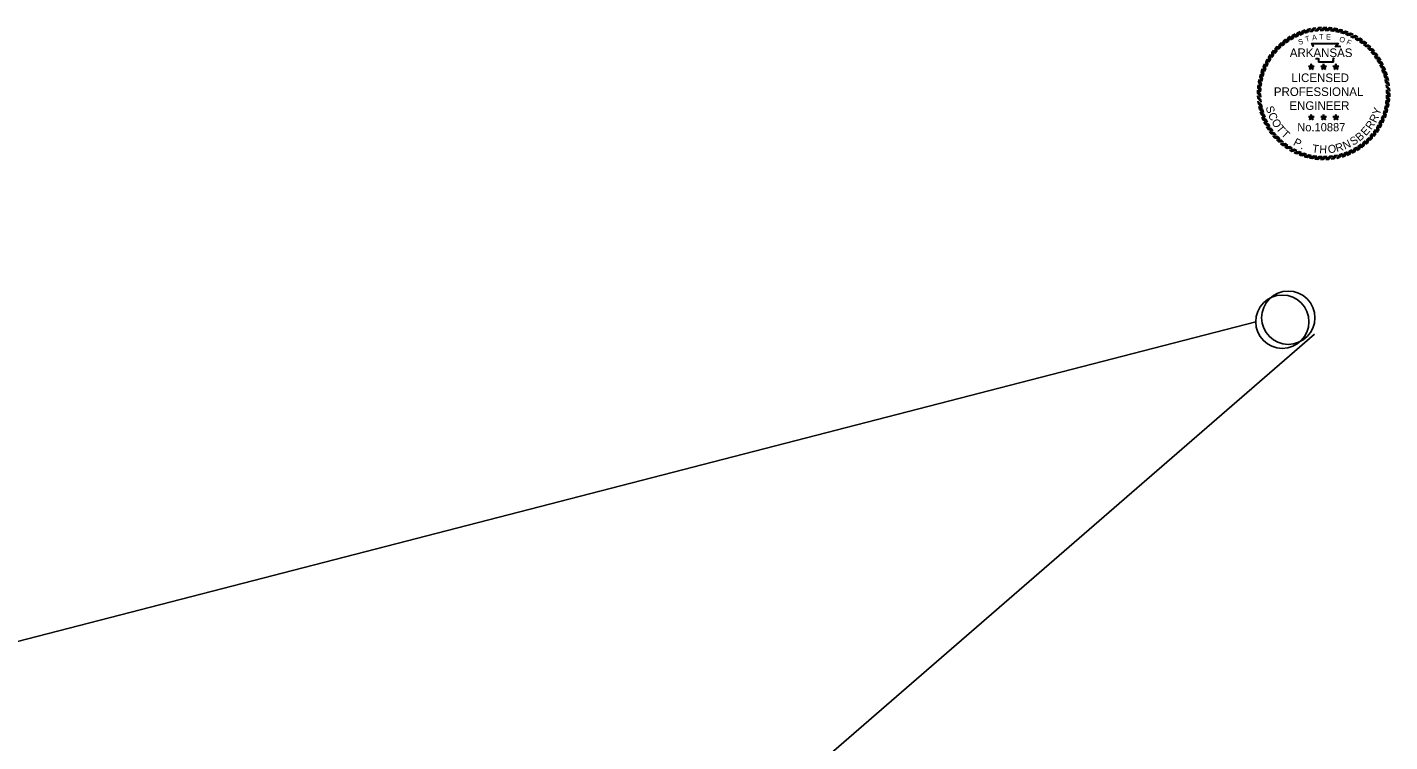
# Model space of a CAD drawing. Extents: x -35254 to 17396, y -8913 to 11592.
# Drawn here: x 736 to 3295, y -769 to 572 of the extents above; entities that cross this region are included whole.
import ezdxf

# ---------------------------------------------------------------- set-up
doc = ezdxf.new("R2010")
doc.units = 0
doc.layers.add('R_Annotation', color=7, linetype='Continuous')
doc.layers.add('STAMP_PP', color=7, linetype='Continuous')

msp = doc.modelspace()

# ---------------------------------------------------------------- linework, layer by layer
at = {"layer": 'R_Annotation'}
for p, q in [((365.7, -671.5), (3043.1, 19)), ((3153.6, -4.4), (1696.8, -1265.6))]:
    msp.add_line(p, q, dxfattribs=at)
for centre in [(3093.1, 19), (3104.3, 26.5)]:
    msp.add_circle(centre, 50, dxfattribs=at)
at = {"layer": 'STAMP_PP'}
for p, q in [((3121.4, 561.3), (3126.4, 563.5)), ((3131, 565), (3136.1, 566.8)), ((3140.9, 567.9), (3146.1, 569.2)), ((3144.6, 562.9), (3150, 563.9)), ((3150.9, 569.9), (3156.3, 570.9)), ((3154.2, 564.7), (3159.7, 565.2)), ((3161.1, 571.1), (3166.5, 571.6)), ((3164, 565.6), (3169.4, 565.6)), ((3171.4, 571.4), (3176.8, 571.4)), ((3173.7, 565.8), (3179.2, 565.4)), ((3181.6, 571), (3187, 570.6)), ((3183.5, 565.1), (3188.9, 564.3)), ((3191.7, 569.7), (3197.1, 568.9)), ((3193.2, 563.7), (3198.5, 562.4)), ((3201.8, 567.5), (3207.1, 566.3)), ((3211.6, 564.6), (3216.8, 562.9)), ((3087.1, 539.1), (3091.1, 542.9)), ((3092.8, 536.6), (3097, 540)), ((3095, 545.7), (3099.2, 549.1)), ((3100.4, 542.7), (3104.9, 545.7)), ((3103.4, 551.6), (3107.9, 554.7)), ((3108.5, 548.2), (3113.3, 550.8)), ((3112.2, 556.8), (3117, 559.5)), ((3117, 553), (3122, 555.2)), ((3125.9, 557), (3131.1, 558.9)), ((3135.1, 560.4), (3140.4, 561.8)), ((3202.7, 561.4), (3207.9, 559.7)), ((3212, 558.4), (3217, 556.2)), ((3221, 554.6), (3225.9, 552)), ((3221.1, 560.8), (3226.1, 558.7)), ((3229.7, 550.1), (3234.3, 547.1)), ((3230.3, 556.2), (3235.1, 553.7)), ((3238, 544.9), (3242.3, 541.5)), ((3239.1, 550.9), (3243.7, 548)), ((3245.8, 539), (3249.9, 535.3)), ((3247.4, 544.9), (3251.7, 541.6)), ((3255.2, 538.3), (3259.2, 534.6)), ((3067.2, 515.8), (3070.1, 520.4)), ((3073.2, 524.1), (3076.5, 528.5)), ((3073.3, 514.7), (3076.6, 519)), ((3079.2, 522.5), (3082.8, 526.6)), ((3079.8, 531.9), (3083.5, 536)), ((3085.7, 529.8), (3089.6, 533.6)), ((3253.1, 532.4), (3256.8, 528.5)), ((3259.9, 525.3), (3263.2, 521.1)), ((3262.4, 531), (3266.1, 527)), ((3266, 517.7), (3269, 513.2)), ((3269, 523.1), (3272.4, 518.9)), ((3274.9, 514.8), (3277.9, 510.2)), ((3053.5, 488.3), (3055.3, 493.5)), ((3057.3, 497.8), (3059.5, 502.8)), ((3059.7, 488.7), (3061.9, 493.7)), ((3061.9, 507), (3064.4, 511.8)), ((3063.5, 497.8), (3066.1, 502.6)), ((3068, 506.4), (3071, 511)), ((3153.1, 498.8), (3142.1, 498.8)), ((3142.1, 498.8), (3151, 492.3)), ((3147.6, 502.8), (3144.2, 492.3)), ((3144.2, 492.3), (3153.1, 498.8)), ((3146.8, 497), (3148.5, 497)), ((3151, 492.3), (3147.6, 502.8)), ((3147.6, 497.6), (3147.6, 496.3)), ((3176.2, 498.8), (3165.2, 498.8)), ((3165.2, 498.8), (3174.1, 492.3)), ((3170.7, 502.8), (3167.3, 492.3)), ((3167.3, 492.3), (3176.2, 498.8)), ((3169.9, 497), (3171.5, 497)), ((3174.1, 492.3), (3170.7, 502.8)), ((3170.7, 497.6), (3170.7, 496.3)), ((3199.3, 498.8), (3188.3, 498.8)), ((3188.3, 498.8), (3197.2, 492.3)), ((3193.8, 502.8), (3190.4, 492.3)), ((3190.4, 492.3), (3199.3, 498.8)), ((3193, 497), (3194.6, 497)), ((3197.2, 492.3), (3193.8, 502.8)), ((3193.8, 497.6), (3193.8, 496.3)), ((3271.5, 509.6), (3274.1, 504.8)), ((3276.3, 501.1), (3278.5, 496.1)), ((3280.1, 505.9), (3282.8, 501.2)), ((3280.3, 492.2), (3282.2, 487)), ((3284.6, 496.7), (3286.8, 491.7)), ((3288.3, 487.1), (3290.1, 482)), ((3047.1, 458.3), (3047.5, 463.7)), ((3048.4, 468.5), (3049.3, 473.8)), ((3050.6, 478.5), (3051.9, 483.8)), ((3053, 460.2), (3053.8, 465.6)), ((3054.4, 469.9), (3055.7, 475.2)), ((3056.7, 479.4), (3058.4, 484.6)), ((3283.7, 483), (3285, 477.7)), ((3286.2, 473.5), (3287.2, 468.1)), ((3288, 463.9), (3288.5, 458.5)), ((3291.1, 477.3), (3292.5, 472)), ((3293.2, 467.2), (3294.1, 461.9)), ((3047, 437.8), (3046.5, 443.2)), ((3046.6, 448), (3046.6, 453.5)), ((3052.3, 450.5), (3052.7, 455.9)), ((3052.5, 440.7), (3052.4, 446.1)), ((3053.4, 430.9), (3052.9, 436.4)), ((3289.1, 444.4), (3288.7, 438.9)), ((3288.9, 454.2), (3289, 448.7)), ((3294.3, 436.5), (3293.9, 431.1)), ((3294.4, 457), (3294.9, 451.6)), ((3294.8, 446.8), (3294.8, 441.3)), ((3048.2, 427.6), (3047.3, 433)), ((3050.3, 417.6), (3048.9, 422.8)), ((3053.1, 407.7), (3051.3, 412.9)), ((3055.2, 421.3), (3054.2, 426.7)), ((3057.7, 411.9), (3056.4, 417.1)), ((3284.7, 415.4), (3283, 410.2)), ((3287, 424.9), (3285.7, 419.6)), ((3288.4, 434.6), (3287.6, 429.2)), ((3290.8, 416.3), (3289.5, 411.1)), ((3293, 426.4), (3292.1, 421)), ((3056.8, 398.1), (3054.6, 403.1)), ((3061.3, 388.9), (3058.6, 393.7)), ((3061.1, 402.7), (3059.2, 407.8)), ((3065.1, 393.8), (3062.9, 398.7)), ((3066.5, 380.1), (3063.5, 384.6)), ((3069.9, 385.2), (3067.3, 390)), ((3153.1, 404.2), (3142.1, 404.2)), ((3142.1, 404.2), (3151, 397.7)), ((3147.6, 408.2), (3144.2, 397.7)), ((3144.2, 397.7), (3153.1, 404.2)), ((3146.8, 402.4), (3148.5, 402.4)), ((3151, 397.7), (3147.6, 408.2)), ((3147.6, 403), (3147.6, 401.6)), ((3176.2, 404.2), (3165.2, 404.2)), ((3165.2, 404.2), (3174.1, 397.7)), ((3170.7, 408.2), (3167.3, 397.7)), ((3167.3, 397.7), (3176.2, 404.2)), ((3169.9, 402.4), (3171.5, 402.4)), ((3174.1, 397.7), (3170.7, 408.2)), ((3170.7, 403), (3170.7, 401.6)), ((3199.3, 404.2), (3188.3, 404.2)), ((3188.3, 404.2), (3197.2, 397.7)), ((3193.8, 408.2), (3190.4, 397.7)), ((3190.4, 397.7), (3199.3, 404.2)), ((3193, 402.4), (3194.6, 402.4)), ((3197.2, 397.7), (3193.8, 408.2)), ((3193.8, 403), (3193.8, 401.6)), ((3273.4, 388.4), (3270.4, 383.8)), ((3277.9, 397.1), (3275.3, 392.2)), ((3279.5, 387.8), (3277, 383)), ((3281.7, 406.1), (3279.5, 401.1)), ((3284.1, 397), (3281.9, 392)), ((3287.9, 406.5), (3286.1, 401.4)), ((3072.4, 371.7), (3069, 376)), ((3075.4, 377.1), (3072.4, 381.6)), ((3079, 363.8), (3075.3, 367.8)), ((3081.5, 369.5), (3078.1, 373.8)), ((3086.2, 356.5), (3082.2, 360.2)), ((3088.3, 362.4), (3084.5, 366.4)), ((3095.6, 355.9), (3091.5, 359.5)), ((3255.7, 365), (3251.8, 361.3)), ((3261.6, 362.9), (3257.9, 358.9)), ((3262.2, 372.3), (3258.6, 368.3)), ((3268.1, 380.1), (3264.8, 375.8)), ((3268.2, 370.7), (3264.9, 366.4)), ((3274.2, 379), (3271.3, 374.4)), ((3094, 349.9), (3089.7, 353.2)), ((3102.3, 343.9), (3097.7, 346.8)), ((3103.4, 350), (3099.1, 353.3)), ((3111.1, 338.6), (3106.3, 341.1)), ((3111.7, 344.8), (3107.1, 347.7)), ((3120.3, 334), (3115.3, 336.2)), ((3120.4, 340.2), (3115.5, 342.8)), ((3129.4, 336.4), (3124.4, 338.6)), ((3138.7, 333.4), (3133.5, 335.1)), ((3206.3, 334.5), (3201, 333.1)), ((3215.5, 337.8), (3210.3, 336)), ((3220, 333.5), (3215, 331.3)), ((3224.4, 341.8), (3219.4, 339.6)), ((3229.2, 338), (3224.4, 335.3)), ((3232.9, 346.6), (3228.1, 344)), ((3238, 343.2), (3233.5, 340.2)), ((3241, 352.1), (3236.5, 349.1)), ((3246.4, 349.1), (3242.2, 345.7)), ((3248.6, 358.3), (3244.4, 354.9)), ((3254.3, 355.7), (3250.3, 352)), ((3129.8, 330.3), (3124.6, 332)), ((3139.6, 327.3), (3134.3, 328.6)), ((3148.2, 331.1), (3142.9, 332.4)), ((3149.6, 325.1), (3144.3, 326)), ((3157.9, 329.7), (3152.5, 330.5)), ((3159.8, 323.8), (3154.4, 324.2)), ((3167.7, 329), (3162.2, 329.4)), ((3170.1, 323.3), (3164.6, 323.3)), ((3177.4, 329.2), (3172, 329.1)), ((3180.3, 323.7), (3174.9, 323.2)), ((3187.2, 330.1), (3181.7, 329.6)), ((3190.5, 324.9), (3185.1, 324)), ((3196.8, 331.9), (3191.4, 331)), ((3200.5, 327), (3195.3, 325.6)), ((3210.4, 329.8), (3205.3, 328))]:
    msp.add_line(p, q, dxfattribs=at)
for points in [[(3122, 555.2), (3126.4, 563.5)], [(3125.9, 557), (3131, 565)], [(3127.6, 557.6), (3132.7, 565.5)], [(3129.4, 558.3), (3134.4, 566.2)], [(3131.1, 558.9), (3136.1, 566.8)], [(3135.1, 560.4), (3140.8, 567.9)], [(3136.8, 560.8), (3142.5, 568.3)], [(3138.7, 561.3), (3144.4, 568.8)], [(3140.4, 561.8), (3146.1, 569.2)], [(3144.6, 562.9), (3150.9, 569.9)], [(3146.3, 563.2), (3152.6, 570.2)], [(3148.2, 563.6), (3154.5, 570.6)], [(3150, 563.9), (3156.3, 570.9)], [(3154.2, 564.7), (3161.1, 571.1)], [(3156, 564.8), (3162.8, 571.3)], [(3157.8, 565), (3164.7, 571.5)], [(3159.6, 565.2), (3166.5, 571.6)], [(3164, 565.6), (3171.4, 571.4)], [(3165.7, 565.6), (3173.1, 571.4)], [(3167.6, 565.7), (3175, 571.5)], [(3169.4, 565.6), (3176.8, 571.4)], [(3173.7, 565.8), (3181.6, 571)], [(3175.5, 565.6), (3183.3, 570.9)], [(3177.4, 565.5), (3185.2, 570.8)], [(3179.2, 565.4), (3187, 570.6)], [(3183.5, 565.1), (3191.7, 569.7)], [(3185.2, 564.8), (3193.5, 569.4)], [(3187.1, 564.6), (3195.3, 569.2)], [(3188.9, 564.3), (3197.1, 568.9)], [(3193.2, 563.7), (3201.8, 567.5)], [(3194.9, 563.2), (3203.5, 567.1)], [(3196.7, 562.8), (3205.3, 566.7)], [(3198.5, 562.4), (3207.1, 566.3)], [(3202.7, 561.4), (3211.6, 564.6)], [(3204.4, 560.9), (3213.2, 564)], [(3206.2, 560.3), (3215, 563.4)], [(3085.7, 529.8), (3087.1, 539.1)], [(3087, 531), (3088.4, 540.3)], [(3088.3, 532.3), (3089.8, 541.6)], [(3089.6, 533.6), (3091.1, 542.9)], [(3092.8, 536.6), (3095, 545.7)], [(3094.1, 537.6), (3096.4, 546.8)], [(3095.6, 538.8), (3097.8, 548)], [(3097, 540), (3099.2, 549.1)], [(3100.4, 542.7), (3103.4, 551.6)], [(3101.9, 543.7), (3104.8, 552.6)], [(3103.4, 544.7), (3106.4, 553.7)], [(3104.9, 545.7), (3107.9, 554.7)], [(3108.5, 548.2), (3112.2, 556.8)], [(3110, 549), (3113.7, 557.7)], [(3111.7, 550), (3115.4, 558.6)], [(3113.3, 550.8), (3117, 559.5)], [(3117, 553), (3121.4, 561.3)], [(3118.6, 553.7), (3123, 562)], [(3120.3, 554.5), (3124.7, 562.8)], [(3151.1, 535), (3148.2, 541.3), (3198.4, 541.3), (3194.2, 536.1), (3197.6, 536.1), (3200.5, 536.1), (3203.3, 535.8)], [(3151.8, 535.4), (3149.5, 540.5), (3196.7, 540.5), (3192.5, 535.2), (3197.6, 535.3), (3200.4, 535.3), (3203.2, 535)], [(3207.9, 559.7), (3216.8, 562.9)], [(3212, 558.4), (3221.1, 560.8)], [(3213.6, 557.7), (3222.7, 560.1)], [(3215.4, 557), (3224.5, 559.4)], [(3217, 556.3), (3226.1, 558.7)], [(3221, 554.6), (3230.3, 556.2)], [(3222.6, 553.8), (3231.8, 555.4)], [(3224.3, 552.9), (3233.5, 554.6)], [(3225.9, 552.1), (3235.1, 553.7)], [(3229.7, 550.1), (3239.1, 550.9)], [(3231.2, 549.1), (3240.6, 550)], [(3232.8, 548.1), (3242.2, 549)], [(3234.3, 547.1), (3243.7, 548)], [(3238, 544.9), (3247.4, 544.9)], [(3239.4, 543.8), (3248.8, 543.9)], [(3240.9, 542.7), (3250.3, 542.8)], [(3242.3, 541.5), (3251.7, 541.6)], [(3245.8, 539), (3255.2, 538.3)], [(3247.1, 537.8), (3256.5, 537.1)], [(3068, 506.4), (3067.2, 515.8)], [(3069, 507.9), (3068.1, 517.3)], [(3070, 509.5), (3069.1, 518.9)], [(3071, 511), (3070.1, 520.4)], [(3073.3, 514.7), (3073.2, 524.1)], [(3074.3, 516.1), (3074.2, 525.5)], [(3075.4, 517.6), (3075.4, 527)], [(3076.6, 519), (3076.5, 528.5)], [(3079.2, 522.5), (3079.8, 531.9)], [(3080.3, 523.8), (3081, 533.2)], [(3081.6, 525.2), (3082.3, 534.6)], [(3082.8, 526.6), (3083.5, 536)], [(3190.5, 514), (3189.6, 513.3), (3189.3, 512.3), (3189.1, 509.7), (3189.1, 506.2), (3161.1, 506.2), (3161.1, 510.9), (3161.1, 511.9), (3159.9, 512.3), (3155.9, 512.3), (3155.2, 513.3)], [(3190, 514.6), (3188.9, 513.7), (3188.6, 512.4), (3188.3, 509.7), (3188.3, 507), (3161.8, 507), (3161.8, 510.9), (3161.8, 512.5), (3160, 513), (3156.4, 513), (3155.9, 513.8)], [(3248.5, 536.5), (3257.9, 535.9)], [(3249.9, 535.3), (3259.2, 534.6)], [(3253.1, 532.4), (3262.4, 531)], [(3254.3, 531.2), (3263.6, 529.7)], [(3255.6, 529.8), (3264.9, 528.4)], [(3256.8, 528.5), (3266.1, 527)], [(3259.9, 525.4), (3269, 523.1)], [(3260.9, 524), (3270.1, 521.8)], [(3262.1, 522.5), (3271.3, 520.3)], [(3263.2, 521.1), (3272.4, 518.9)], [(3266, 517.7), (3274.9, 514.8)], [(3266.9, 516.3), (3275.9, 513.3)], [(3268, 514.7), (3277, 511.7)], [(3269, 513.2), (3278, 510.2)], [(3056.7, 479.4), (3053.5, 488.3)], [(3057.3, 481.1), (3054.1, 490)], [(3057.8, 482.9), (3054.7, 491.8)], [(3058.4, 484.6), (3055.3, 493.5)], [(3059.7, 488.7), (3057.3, 497.8)], [(3060.4, 490.3), (3058, 499.4)], [(3061.1, 492.1), (3058.7, 501.2)], [(3061.9, 493.7), (3059.5, 502.8)], [(3063.5, 497.8), (3061.9, 507)], [(3064.3, 499.3), (3062.7, 508.6)], [(3065.2, 501), (3063.5, 510.3)], [(3066.1, 502.6), (3064.4, 511.8)], [(3271.5, 509.6), (3280.1, 505.9)], [(3272.3, 508.1), (3281, 504.4)], [(3273.2, 506.4), (3281.9, 502.7)], [(3274.1, 504.8), (3282.8, 501.2)], [(3276.3, 501.1), (3284.6, 496.7)], [(3277, 499.5), (3285.3, 495.1)], [(3277.8, 497.8), (3286.1, 493.4)], [(3278.5, 496.1), (3286.8, 491.7)], [(3280.3, 492.2), (3288.3, 487.1)], [(3280.9, 490.5), (3288.8, 485.5)], [(3281.6, 488.8), (3289.5, 483.7)], [(3282.2, 487), (3290.1, 482)], [(3052.6, 454.1), (3047.3, 461.9)], [(3052.7, 455.9), (3047.5, 463.7)], [(3053, 460.2), (3048.4, 468.5)], [(3053.3, 461.9), (3048.7, 470.2)], [(3053.5, 463.8), (3049, 472.1)], [(3053.8, 465.6), (3049.3, 473.8)], [(3054.4, 469.9), (3050.6, 478.5)], [(3054.9, 471.6), (3051, 480.2)], [(3055.3, 473.4), (3051.4, 482)], [(3055.7, 475.2), (3051.8, 483.8)], [(3283.6, 483), (3291.1, 477.3)], [(3284.1, 481.3), (3291.6, 475.6)], [(3284.6, 479.5), (3292.1, 473.8)], [(3285, 477.7), (3292.5, 472)], [(3286.2, 473.5), (3293.2, 467.2)], [(3286.5, 471.8), (3293.5, 465.5)], [(3286.9, 469.9), (3293.8, 463.6)], [(3287.2, 468.2), (3294.1, 461.9)], [(3288, 463.9), (3294.4, 457)], [(3288.1, 462.2), (3294.6, 455.3)], [(3052.9, 436.4), (3046.5, 443.2)], [(3052.4, 446.1), (3046.6, 453.5)], [(3052.4, 444.3), (3046.6, 451.7)], [(3052.5, 442.4), (3046.6, 449.8)], [(3052.5, 440.7), (3046.6, 448)], [(3053.1, 434.6), (3046.6, 441.4)], [(3053.3, 432.7), (3046.8, 439.5)], [(3053.4, 430.9), (3047, 437.8)], [(3052.3, 450.5), (3047.1, 458.3)], [(3052.5, 452.2), (3047.2, 460)], [(3288.3, 460.3), (3294.8, 453.4)], [(3288.5, 458.5), (3294.9, 451.6)], [(3288.7, 438.9), (3293.9, 431.1)], [(3288.8, 440.7), (3294.1, 432.9)], [(3288.9, 454.2), (3294.8, 446.8)], [(3288.9, 452.4), (3294.8, 445)], [(3288.9, 442.6), (3294.2, 434.8)], [(3289, 450.5), (3294.8, 443.1)], [(3289, 448.7), (3294.8, 441.3)], [(3289.1, 444.4), (3294.3, 436.5)], [(3054.2, 426.7), (3047.2, 433)], [(3054.5, 424.9), (3047.5, 431.2)], [(3054.9, 423), (3047.9, 429.3)], [(3055.2, 421.3), (3048.2, 427.6)], [(3056.4, 417.1), (3048.9, 422.8)], [(3056.8, 415.4), (3049.3, 421.1)], [(3057.3, 413.6), (3049.8, 419.3)], [(3057.7, 411.9), (3050.3, 417.6)], [(3059.2, 407.8), (3051.3, 412.9)], [(3059.8, 406.1), (3051.9, 411.1)], [(3283, 410.2), (3286.1, 401.4)], [(3283.6, 411.9), (3286.7, 403.1)], [(3284.1, 413.7), (3287.3, 404.9)], [(3284.7, 415.4), (3287.9, 406.5)], [(3285.7, 419.6), (3289.5, 411)], [(3286.1, 421.4), (3290, 412.8)], [(3286.5, 423.2), (3290.4, 414.6)], [(3287, 424.9), (3290.8, 416.3)], [(3287.6, 429.2), (3292.1, 421)], [(3287.9, 431), (3292.4, 422.8)], [(3288.1, 432.9), (3292.7, 424.6)], [(3288.4, 434.6), (3293, 426.4)], [(3060.5, 404.3), (3052.6, 409.4)], [(3061.1, 402.6), (3053.1, 407.7)], [(3062.9, 398.7), (3054.6, 403.1)], [(3063.6, 397.1), (3055.3, 401.5)], [(3064.4, 395.4), (3056.1, 399.7)], [(3065.1, 393.7), (3056.8, 398.1)], [(3067.3, 390), (3058.6, 393.7)], [(3068.1, 388.4), (3059.5, 392.1)], [(3069.1, 386.8), (3060.4, 390.4)], [(3069.9, 385.2), (3061.3, 388.9)], [(3072.4, 381.6), (3063.4, 384.6)], [(3271.4, 385.3), (3272.3, 375.9)], [(3272.4, 386.9), (3273.3, 377.6)], [(3273.4, 388.4), (3274.2, 379)], [(3275.3, 392.3), (3277, 383)], [(3276.2, 393.8), (3277.8, 384.6)], [(3277.1, 395.5), (3278.7, 386.3)], [(3277.9, 397.1), (3279.5, 387.8)], [(3279.5, 401.1), (3281.9, 392)], [(3280.3, 402.7), (3282.7, 393.6)], [(3281, 404.5), (3283.4, 395.4)], [(3281.7, 406.1), (3284.1, 397)], [(3073.4, 380.1), (3064.4, 383.1)], [(3074.5, 378.6), (3065.5, 381.5)], [(3075.4, 377.1), (3066.5, 380.1)], [(3078.1, 373.7), (3069, 376)], [(3079.3, 372.3), (3070.1, 374.5)], [(3080.5, 370.9), (3071.3, 373.1)], [(3081.5, 369.5), (3072.4, 371.7)], [(3084.5, 366.4), (3075.2, 367.8)], [(3085.8, 365), (3076.5, 366.5)], [(3087.1, 363.7), (3077.8, 365.1)], [(3088.3, 362.4), (3079, 363.8)], [(3091.5, 359.5), (3082.1, 360.2)], [(3092.9, 358.3), (3083.5, 359)], [(3251.8, 361.3), (3250.3, 352)], [(3253.1, 362.5), (3251.6, 353.2)], [(3254.4, 363.8), (3253, 354.5)], [(3255.7, 365), (3254.3, 355.7)], [(3258.6, 368.3), (3257.9, 358.9)], [(3259.8, 369.6), (3259.1, 360.2)], [(3261.1, 371), (3260.4, 361.6)], [(3262.2, 372.3), (3261.6, 362.9)], [(3264.8, 375.8), (3264.9, 366.4)], [(3265.9, 377.2), (3266, 367.8)], [(3267.1, 378.7), (3267.2, 369.3)], [(3268.1, 380.1), (3268.2, 370.7)], [(3270.4, 383.8), (3271.3, 374.4)], [(3094.3, 357.1), (3084.9, 357.7)], [(3095.6, 355.9), (3086.2, 356.5)], [(3099.1, 353.3), (3089.7, 353.2)], [(3100.5, 352.2), (3091.1, 352.1)], [(3102, 351.1), (3092.6, 351)], [(3103.4, 350), (3094, 349.9)], [(3107.1, 347.7), (3097.7, 346.8)], [(3108.6, 346.7), (3099.2, 345.8)], [(3110.2, 345.7), (3100.8, 344.8)], [(3111.7, 344.8), (3102.3, 343.9)], [(3115.5, 342.8), (3106.3, 341.1)], [(3117.1, 341.9), (3107.9, 340.3)], [(3118.8, 341.1), (3109.6, 339.4)], [(3120.4, 340.2), (3111.1, 338.6)], [(3124.4, 338.6), (3115.3, 336.2)], [(3126, 337.8), (3116.9, 335.4)], [(3127.8, 337.1), (3118.7, 334.7)], [(3129.4, 336.4), (3120.3, 334)], [(3133.5, 335.1), (3124.6, 332)], [(3135.2, 334.5), (3126.4, 331.4)], [(3137, 334), (3128.2, 330.8)], [(3138.7, 333.4), (3129.8, 330.3)], [(3201, 333.1), (3195.3, 325.6)], [(3202.7, 333.5), (3197, 326)], [(3204.6, 334), (3198.9, 326.5)], [(3206.3, 334.5), (3200.6, 327)], [(3210.3, 336), (3205.3, 328)], [(3212, 336.5), (3207, 328.6)], [(3213.8, 337.2), (3208.7, 329.3)], [(3215.5, 337.8), (3210.4, 329.9)], [(3219.4, 339.6), (3215, 331.3)], [(3221.1, 340.3), (3216.7, 332)], [(3222.8, 341.2), (3218.4, 332.8)], [(3224.4, 341.9), (3220, 333.5)], [(3228.1, 344), (3224.4, 335.3)], [(3229.7, 344.9), (3226, 336.2)], [(3231.4, 345.8), (3227.7, 337.2)], [(3232.9, 346.6), (3229.2, 338)], [(3236.5, 349.1), (3233.5, 340.2)], [(3238, 350.1), (3235, 341.2)], [(3239.5, 351.2), (3236.6, 342.2)], [(3241, 352.1), (3238, 343.2)], [(3244.4, 354.9), (3242.2, 345.7)], [(3245.8, 356), (3243.6, 346.8)], [(3247.3, 357.2), (3245, 348)], [(3248.6, 358.3), (3246.4, 349.1)], [(3142.9, 332.4), (3134.3, 328.6)], [(3144.7, 332), (3136.1, 328.1)], [(3146.5, 331.6), (3137.9, 327.7)], [(3148.2, 331.2), (3139.6, 327.3)], [(3152.5, 330.5), (3144.3, 326)], [(3154.3, 330.2), (3146.1, 325.7)], [(3156.2, 330), (3147.9, 325.4)], [(3157.9, 329.7), (3149.7, 325.1)], [(3162.2, 329.4), (3154.4, 324.2)], [(3164, 329.3), (3156.2, 324)], [(3165.9, 329.2), (3158.1, 324)], [(3167.7, 329), (3159.8, 323.8)], [(3172, 329.1), (3164.6, 323.3)], [(3173.8, 329.1), (3166.4, 323.3)], [(3175.7, 329.2), (3168.3, 323.3)], [(3177.4, 329.2), (3170.1, 323.3)], [(3181.8, 329.6), (3174.9, 323.2)], [(3183.6, 329.8), (3176.7, 323.3)], [(3185.4, 330), (3178.6, 323.6)], [(3187.2, 330.1), (3180.3, 323.7)], [(3191.4, 331), (3185.1, 324)], [(3193.2, 331.3), (3186.9, 324.3)], [(3195.1, 331.6), (3188.8, 324.6)], [(3196.8, 331.9), (3190.5, 324.9)]]:
    msp.add_lwpolyline(points, dxfattribs=at)

# ---------------------------------------------------------------- texts
for s, height, rotation, p in [('S', 9.9, 19.7726, (3125, 538.3)), ('T', 9.9, 16.9015, (3137.6, 544)), ('A', 9.9, 8.6788, (3149.6, 547.1)), ('T', 9.9, 1.4789, (3162.4, 549.1)), ('E', 9.9, 356.672, (3175, 548.8)), ('O', 9.9, 341.2218, (3199.1, 545.4)), ('F', 9.9, 335.3628, (3212.4, 540.2)), ('S', 15, 286.9475, (3061.6, 421.5)), ('C', 15, 294.2435, (3065.8, 407.8)), ('Y', 15, 71.7733, (3275.8, 405.4)), ('O', 15, 301.9044, (3072, 394.1)), ('T', 15, 309.93, (3080.4, 380.7)), ('E', 15, 48.0613, (3250.1, 366.9)), ('R', 15, 55.7221, (3260.1, 378.2)), ('R', 15, 63.7477, (3268.9, 391.2)), ('T', 15, 317.226, (3089.6, 369.7)), ('P', 15, 332.1828, (3112.4, 351.3)), ('N', 15, 23.9845, (3210.4, 341.8)), ('S', 15, 32.7397, (3226, 349)), ('B', 15, 40.0357, (3238.1, 356.7)), ('.', 15, 340.2084, (3126.4, 344)), ('T', 15, 351.882, (3148.3, 337.1)), ('H', 15, 359.178, (3162.5, 335.1)), ('O', 15, 7.9332, (3179.7, 335.1)), ('R', 15, 15.9589, (3195.3, 337.3))]:
    msp.add_text(s, height=height, rotation=rotation, dxfattribs=at).set_placement(p)
for s, height, p in [('ARKANSAS', 16.15, (3107.2, 515.8)), ('LICENSED', 16.15, (3110.3, 468.8)), ('PROFESSIONAL', 16.155, (3077.2, 442.7)), ('ENGINEER', 16.15, (3106.4, 416.5)), ('No.10887', 15.58, (3121.2, 376.3))]:
    msp.add_text(s, height=height, dxfattribs=at).set_placement(p)

doc.saveas('drawing.dxf')
